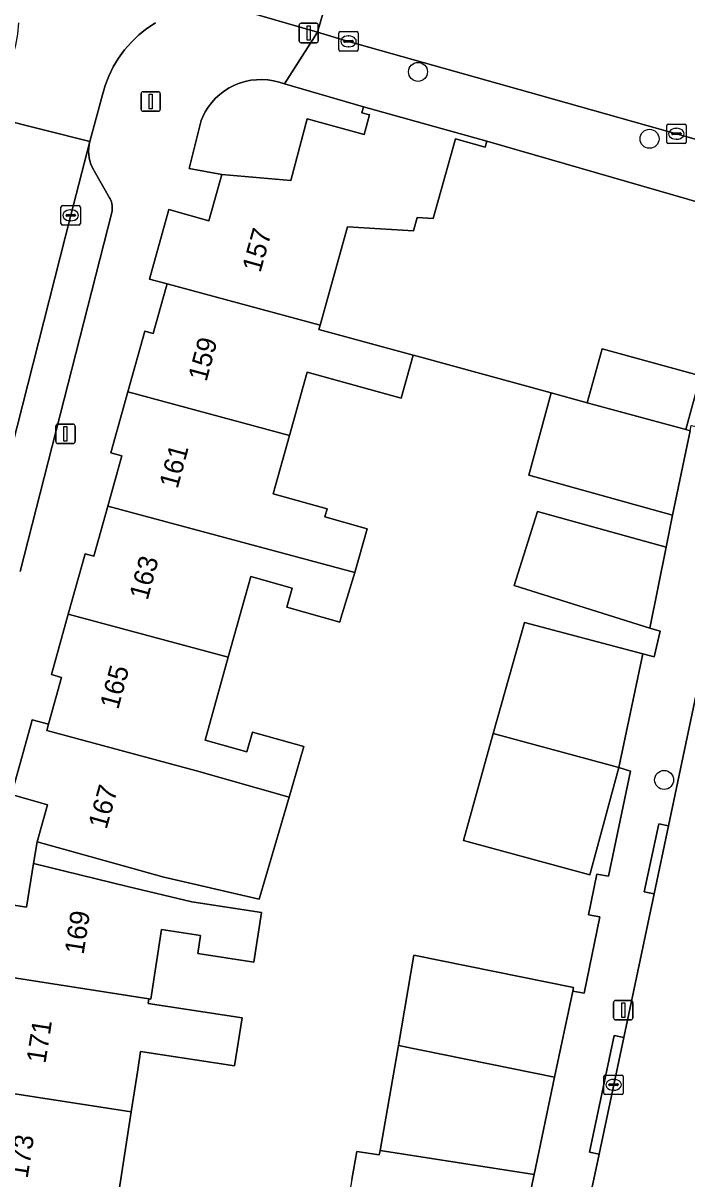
# Model space of a CAD drawing. Extents: x 161248 to 161848, y 384871 to 385383.
# Drawn here: x 161671 to 161705.2, y 385039.6 to 385099.1 of the extents above; entities that cross this region are included whole.
import ezdxf

# ---------------------------------------------------------------- set-up
doc = ezdxf.new("R2010")
doc.units = 0
for name, color, linetype in [('IMGEO_Boom', 7, 'Continuous'), ('IMGEO_Erf', 7, 'Continuous'), ('IMGEO_Hek', 7, 'Continuous'), ('IMGEO_Kolk', 7, 'Continuous'), ('IMGEO_Lichtmast', 7, 'Continuous'), ('IMGEO_Pand', 7, 'Continuous'), ('IMGEO_Pand_nummerreeks', 7, 'Continuous'), ('IMGEO_Parkeervlak_open', 7, 'Continuous'), ('IMGEO_Rijbaan_lokaal_open', 7, 'Continuous'), ('IMGEO_Voetpad_open', 7, 'Continuous')]:
    doc.layers.add(name, color=color, linetype=linetype)

msp = doc.modelspace()

# ---------------------------------------------------------------- linework, layer by layer
at = {"layer": 'IMGEO_Boom'}
for centre in [(161691.332, 385096.626), (161703.264, 385093.176), (161704.015, 385060.129)]:
    msp.add_circle(centre, 0.489, dxfattribs=at)
at = {"layer": 'IMGEO_Erf'}
for points in [[(161688.519, 385094.827), (161684.448, 385096.001), (161684.17, 385096.097), (161683.884, 385096.168), (161683.592, 385096.213), (161683.298, 385096.232), (161683.003, 385096.224), (161682.71, 385096.19), (161682.422, 385096.13), (161682.14, 385096.045), (161681.866, 385095.935), (161681.604, 385095.801), (161681.354, 385095.643), (161681.12, 385095.465), (161680.902, 385095.266), (161680.704, 385095.048), (161680.525, 385094.813), (161680.368, 385094.564), (161680.234, 385094.301), (161680.159, 385094.122), (161679.542, 385091.647), (161681.223, 385091.339), (161684.77, 385091.03), (161685.625, 385094.2), (161688.558, 385093.404), (161688.837, 385094.406), (161688.433, 385094.519)], [(161707.725, 385089.351), (161694.886, 385093.053), (161694.8, 385092.745), (161693.259, 385093.174), (161692.116, 385089.073), (161691.294, 385089.125), (161691.1, 385088.429), (161687.699, 385088.644), (161686.286, 385083.569), (161686.225, 385083.351), (161691.078, 385082.026), (161691.283, 385081.97), (161698.188, 385080.085), (161700.058, 385079.574), (161700.815, 385082.347), (161705.891, 385080.961), (161705.134, 385078.188), (161705.35, 385078.129), (161705.415, 385078.403), (161706.001, 385078.274), (161706.582, 385080.923), (161705.996, 385081.052)]]:
    msp.add_lwpolyline(points, close=True, dxfattribs=at)
msp.add_lwpolyline([(161687.923, 385039.536), (161688.171, 385040.983), (161689.338, 385040.81), (161689.376, 385041.027), (161690.323, 385046.434), (161691.123, 385051.093), (161699.354, 385049.432), (161699.313, 385049.242), (161699.897, 385049.131), (161700.704, 385053.073), (161700.114, 385053.185), (161700.543, 385055.277), (161701.146, 385055.163), (161702.28, 385060.59), (161701.685, 385060.766), (161700.183, 385055.247), (161693.674, 385057.017), (161695.208, 385062.528), (161696.828, 385068.247), (161702.916, 385066.622), (161703.511, 385066.476), (161703.805, 385067.793), (161703.28, 385067.948), (161696.289, 385070.15), (161697.492, 385073.969), (161704.117, 385072.125), (161704.441, 385073.771), (161697.038, 385075.832), (161698.188, 385080.085), (161691.283, 385081.97), (161691.078, 385082.026), (161690.459, 385079.804), (161685.613, 385081.154), (161684.703, 385077.885), (161683.867, 385074.884), (161686.648, 385074.109), (161686.53, 385073.686), (161688.704, 385073.081), (161688.074, 385070.82), (161687.355, 385068.461), (161687.301, 385068.267), (161684.57, 385069.027), (161684.846, 385070.018), (161682.712, 385070.612), (161681.553, 385066.451), (161680.364, 385062.179), (161682.518, 385061.579), (161682.801, 385062.595), (161685.451, 385061.857), (161684.685, 385059.25), (161683.137, 385053.977), (161678.383, 385055.084), (161678.24, 385055.117), (161676.52, 385055.596), (161671.703, 385056.938), (161671.506, 385055.82), (161676.367, 385054.646), (161679.669, 385053.849), (161683.273, 385053.291), (161682.878, 385050.741), (161679.981, 385051.189), (161680.123, 385052.108), (161678.111, 385052.42), (161677.556, 385048.836), (161677.453, 385048.852), (161677.416, 385048.614), (161682.266, 385047.863), (161681.882, 385045.387), (161677.033, 385046.137), (161676.885, 385045.183), (161676.55, 385043.02), (161675.859, 385038.559)], dxfattribs=at)
at = {"layer": 'IMGEO_Hek'}
for points in [[(161704.441, 385073.771), (161704.117, 385072.125)], [(161703.28, 385067.948), (161703.805, 385067.793), (161703.511, 385066.476), (161702.916, 385066.622)], [(161701.685, 385060.766), (161702.28, 385060.59), (161701.146, 385055.163), (161700.543, 385055.277), (161700.114, 385053.185), (161700.704, 385053.073), (161699.897, 385049.131), (161699.307, 385049.243), (161698.363, 385044.812)]]:
    msp.add_lwpolyline(points, dxfattribs=at)
at = {"layer": 'IMGEO_Kolk'}
for p, q in [((161687.251, 385097.773), (161687.251, 385098.625)), ((161687.326, 385098.699), (161688.178, 385098.699)), ((161687.51, 385098.193), (161687.51, 385098.205)), ((161687.553, 385098.242), (161687.951, 385098.242)), ((161687.739, 385098.479), (161687.764, 385098.479)), ((161687.994, 385098.205), (161687.994, 385098.193)), ((161688.252, 385098.625), (161688.252, 385097.773)), ((161688.178, 385097.699), (161687.326, 385097.699)), ((161687.948, 385098.156), (161687.55, 385098.156)), ((161687.762, 385097.919), (161687.737, 385097.919)), ((161704.15, 385093.01), (161704.15, 385093.862)), ((161704.225, 385093.936), (161705.077, 385093.936)), ((161704.409, 385093.43), (161704.409, 385093.442)), ((161704.452, 385093.479), (161704.85, 385093.479)), ((161704.638, 385093.716), (161704.663, 385093.716)), ((161704.893, 385093.442), (161704.893, 385093.43)), ((161705.151, 385093.862), (161705.151, 385093.01)), ((161705.077, 385092.936), (161704.225, 385092.936)), ((161704.847, 385093.393), (161704.449, 385093.393)), ((161704.661, 385093.156), (161704.636, 385093.156)), ((161672.931, 385088.806), (161672.931, 385089.658)), ((161673.006, 385089.732), (161673.858, 385089.732)), ((161673.233, 385089.275), (161673.631, 385089.275)), ((161673.419, 385089.512), (161673.444, 385089.512)), ((161673.932, 385089.658), (161673.932, 385088.806)), ((161673.858, 385088.732), (161673.006, 385088.732)), ((161673.19, 385089.226), (161673.19, 385089.238)), ((161673.628, 385089.189), (161673.23, 385089.189)), ((161673.442, 385088.952), (161673.417, 385088.952)), ((161673.674, 385089.238), (161673.674, 385089.226)), ((161700.91, 385043.992), (161700.91, 385044.844)), ((161700.985, 385044.918), (161701.837, 385044.918)), ((161701.398, 385044.698), (161701.423, 385044.698)), ((161701.911, 385044.844), (161701.911, 385043.992)), ((161701.169, 385044.412), (161701.169, 385044.424)), ((161701.607, 385044.375), (161701.209, 385044.375)), ((161701.212, 385044.461), (161701.61, 385044.461)), ((161701.421, 385044.138), (161701.396, 385044.138)), ((161701.653, 385044.424), (161701.653, 385044.412)), ((161701.837, 385043.918), (161700.985, 385043.918))]:
    msp.add_line(p, q, dxfattribs=at)
for points in [[(161687.251, 385097.773), (161687.251, 385098.625)], [(161687.326, 385098.699), (161688.178, 385098.699)], [(161688.252, 385098.625), (161688.252, 385097.773)], [(161688.178, 385097.699), (161687.326, 385097.699)], [(161704.15, 385093.01), (161704.15, 385093.862)], [(161704.225, 385093.936), (161705.077, 385093.936)], [(161705.151, 385093.862), (161705.151, 385093.01)], [(161705.077, 385092.936), (161704.225, 385092.936)], [(161672.931, 385088.806), (161672.931, 385089.658)], [(161673.006, 385089.732), (161673.858, 385089.732)], [(161673.932, 385089.658), (161673.932, 385088.806)], [(161673.858, 385088.732), (161673.006, 385088.732)], [(161700.91, 385043.992), (161700.91, 385044.844)], [(161700.985, 385044.918), (161701.837, 385044.918)], [(161701.911, 385044.844), (161701.911, 385043.992)], [(161701.837, 385043.918), (161700.985, 385043.918)]]:
    msp.add_lwpolyline(points, dxfattribs=at)
for centre, radius, start, end in [((161687.328, 385098.623), 0.0765, 91.55205, 178.44795), ((161687.328, 385098.623), 0.0765, 91.55205, 178.44795), ((161687.55, 385098.202), 0.0403, 85.87752, 175.75265), ((161687.955, 385098.204), 0.0386, 1.73085, 96.63898), ((161688.176, 385098.623), 0.0765, 1.55205, 88.44795), ((161688.176, 385098.623), 0.0765, 1.55205, 88.44795), ((161687.328, 385097.775), 0.0765, 181.55205, 268.44795), ((161687.328, 385097.775), 0.0765, 181.55205, 268.44795), ((161687.547, 385098.192), 0.0366, 178.93798, 274.71019), ((161687.951, 385098.199), 0.043, 264.86636, 352.45326), ((161688.176, 385097.775), 0.0765, 271.55205, 358.44795), ((161688.176, 385097.775), 0.0765, 271.55205, 358.44795), ((161704.227, 385093.86), 0.0765, 91.55205, 178.44795), ((161704.227, 385093.86), 0.0765, 91.55205, 178.44795), ((161704.449, 385093.439), 0.0403, 85.87752, 175.75265), ((161704.854, 385093.441), 0.0386, 1.73085, 96.63898), ((161705.075, 385093.86), 0.0765, 1.55205, 88.44795), ((161705.075, 385093.86), 0.0765, 1.55205, 88.44795), ((161704.227, 385093.012), 0.0765, 181.55205, 268.44795), ((161704.227, 385093.012), 0.0765, 181.55205, 268.44795), ((161704.446, 385093.429), 0.0366, 178.93798, 274.71019), ((161704.85, 385093.436), 0.043, 264.86636, 352.45326), ((161705.075, 385093.012), 0.0765, 271.55205, 358.44795), ((161705.075, 385093.012), 0.0765, 271.55205, 358.44795), ((161673.008, 385089.656), 0.0765, 91.55205, 178.44795), ((161673.008, 385089.656), 0.0765, 91.55205, 178.44795), ((161673.23, 385089.235), 0.0403, 85.87752, 175.75265), ((161673.635, 385089.237), 0.0386, 1.73085, 96.63898), ((161673.856, 385089.656), 0.0765, 1.55205, 88.44795), ((161673.856, 385089.656), 0.0765, 1.55205, 88.44795), ((161673.008, 385088.808), 0.0765, 181.55205, 268.44795), ((161673.008, 385088.808), 0.0765, 181.55205, 268.44795), ((161673.227, 385089.225), 0.0366, 178.93798, 274.71019), ((161673.631, 385089.232), 0.043, 264.86636, 352.45326), ((161673.856, 385088.808), 0.0765, 271.55205, 358.44795), ((161673.856, 385088.808), 0.0765, 271.55205, 358.44795), ((161700.987, 385044.842), 0.0765, 91.55205, 178.44795), ((161700.987, 385044.842), 0.0765, 91.55205, 178.44795), ((161701.835, 385044.842), 0.0765, 1.55205, 88.44795), ((161701.835, 385044.842), 0.0765, 1.55205, 88.44795), ((161700.987, 385043.994), 0.0765, 181.55205, 268.44795), ((161700.987, 385043.994), 0.0765, 181.55205, 268.44795), ((161701.209, 385044.421), 0.0403, 85.87752, 175.75265), ((161701.206, 385044.411), 0.0366, 178.93798, 274.71019), ((161701.61, 385044.418), 0.043, 264.86636, 352.45326), ((161701.614, 385044.423), 0.0386, 1.73085, 96.63898), ((161701.835, 385043.994), 0.0765, 271.55205, 358.44795), ((161701.835, 385043.994), 0.0765, 271.55205, 358.44795)]:
    msp.add_arc(centre, radius, start, end, dxfattribs=at)
for centre, major_axis, ratio, start_param, end_param in [((161687.738, 385098.199), (-0.387, 0.002), 0.722429, 4.712389, 7.853982), ((161687.763, 385098.199), (-0.39, 0.002), 0.717154, 1.570796, 4.712389), ((161704.637, 385093.436), (-0.387, 0.002), 0.722429, 4.712389, 7.853982), ((161704.662, 385093.436), (-0.39, 0.002), 0.717154, 1.570796, 4.712389), ((161673.418, 385089.232), (-0.387, 0.002), 0.722429, 4.712389, 7.853982), ((161673.443, 385089.232), (-0.39, 0.002), 0.717154, 1.570796, 4.712389), ((161701.397, 385044.418), (-0.387, 0.002), 0.722429, 4.712389, 7.853982), ((161701.422, 385044.418), (-0.39, 0.002), 0.717154, 1.570796, 4.712389)]:
    msp.add_ellipse(centre, major_axis=major_axis, ratio=ratio, start_param=start_param, end_param=end_param, dxfattribs=at)
at = {"layer": 'IMGEO_Lichtmast'}
for p, q in [((161685.204, 385098.228), (161685.204, 385099.028)), ((161685.204, 385099.028), (161685.204, 385098.228)), ((161685.304, 385099.128), (161686.094, 385099.128)), ((161686.094, 385099.128), (161685.304, 385099.128)), ((161686.194, 385099.028), (161686.194, 385098.228)), ((161686.194, 385098.228), (161686.194, 385099.028)), ((161686.094, 385098.128), (161685.304, 385098.128)), ((161685.304, 385098.128), (161686.094, 385098.128)), ((161677.059, 385094.699), (161677.059, 385095.499)), ((161677.059, 385095.499), (161677.059, 385094.699)), ((161677.159, 385095.599), (161677.949, 385095.599)), ((161677.949, 385095.599), (161677.159, 385095.599)), ((161678.049, 385095.499), (161678.049, 385094.699)), ((161678.049, 385094.699), (161678.049, 385095.499)), ((161677.949, 385094.599), (161677.159, 385094.599)), ((161677.159, 385094.599), (161677.949, 385094.599)), ((161672.664, 385077.568), (161672.664, 385078.368)), ((161672.664, 385078.368), (161672.664, 385077.568)), ((161672.764, 385078.468), (161673.554, 385078.468)), ((161673.554, 385078.468), (161672.764, 385078.468)), ((161673.654, 385078.368), (161673.654, 385077.568)), ((161673.654, 385077.568), (161673.654, 385078.368)), ((161673.554, 385077.468), (161672.764, 385077.468)), ((161672.764, 385077.468), (161673.554, 385077.468)), ((161701.514, 385048.765), (161702.304, 385048.765)), ((161702.304, 385048.765), (161701.514, 385048.765)), ((161701.414, 385047.865), (161701.414, 385048.665)), ((161701.414, 385048.665), (161701.414, 385047.865)), ((161702.404, 385048.665), (161702.404, 385047.865)), ((161702.404, 385047.865), (161702.404, 385048.665)), ((161702.304, 385047.765), (161701.514, 385047.765)), ((161701.514, 385047.765), (161702.304, 385047.765))]:
    msp.add_line(p, q, dxfattribs=at)
for points in [[(161685.624, 385099.003), (161685.774, 385099.003), (161685.774, 385098.253), (161685.624, 385098.253), (161685.624, 385099.003)], [(161677.479, 385095.474), (161677.629, 385095.474), (161677.629, 385094.724), (161677.479, 385094.724), (161677.479, 385095.474)], [(161673.084, 385078.343), (161673.234, 385078.343), (161673.234, 385077.593), (161673.084, 385077.593), (161673.084, 385078.343)], [(161701.834, 385048.64), (161701.984, 385048.64), (161701.984, 385047.89), (161701.834, 385047.89), (161701.834, 385048.64)]]:
    msp.add_lwpolyline(points, dxfattribs=at)
for centre, start, end in [((161685.304, 385099.028), 90, 180), ((161685.304, 385099.028), 90, 180), ((161686.094, 385099.028), 0, 90), ((161686.094, 385099.028), 360, 90), ((161685.304, 385098.228), 180, 270), ((161685.304, 385098.228), 180, 270), ((161686.094, 385098.228), 270, 0), ((161686.094, 385098.228), 270, 0), ((161677.159, 385095.499), 90, 180), ((161677.159, 385095.499), 90, 180), ((161677.949, 385095.499), 0, 90), ((161677.949, 385095.499), 360, 90), ((161677.159, 385094.699), 180, 270), ((161677.159, 385094.699), 180, 270), ((161677.949, 385094.699), 270, 0), ((161677.949, 385094.699), 270, 0), ((161672.764, 385078.368), 90, 180), ((161672.764, 385078.368), 90, 180), ((161673.554, 385078.368), 0, 90), ((161673.554, 385078.368), 360, 90), ((161672.764, 385077.568), 180, 270), ((161672.764, 385077.568), 180, 270), ((161673.554, 385077.568), 270, 0), ((161673.554, 385077.568), 270, 0), ((161701.514, 385048.665), 90, 180), ((161701.514, 385048.665), 90, 180), ((161702.304, 385048.665), 0, 90), ((161702.304, 385048.665), 360, 90), ((161701.514, 385047.865), 180, 270), ((161701.514, 385047.865), 180, 270), ((161702.304, 385047.865), 270, 0), ((161702.304, 385047.865), 270, 0)]:
    msp.add_arc(centre, 0.1, start, end, dxfattribs=at)
at = {"layer": 'IMGEO_Pand'}
for points in [[(161693.259, 385093.174), (161694.8, 385092.745), (161694.886, 385093.053), (161688.519, 385094.827), (161688.433, 385094.519), (161688.837, 385094.406), (161688.558, 385093.404), (161685.625, 385094.2), (161684.77, 385091.03), (161681.223, 385091.339), (161680.558, 385088.951), (161678.492, 385089.527), (161677.492, 385085.936), (161678.395, 385085.693), (161686.286, 385083.569), (161687.699, 385088.644), (161691.1, 385088.429), (161691.294, 385089.125), (161692.116, 385089.073)], [(161686.225, 385083.351), (161686.286, 385083.569), (161678.395, 385085.693), (161678.35, 385085.532), (161677.683, 385083.137), (161677.244, 385083.26), (161676.371, 385080.127), (161684.703, 385077.885), (161685.613, 385081.154), (161690.459, 385079.804), (161691.078, 385082.026)], [(161700.058, 385079.574), (161705.134, 385078.188), (161705.891, 385080.961), (161700.815, 385082.347)], [(161684.703, 385077.885), (161676.371, 385080.127), (161675.499, 385076.995), (161676.061, 385076.838), (161675.339, 385074.248), (161688.074, 385070.82), (161688.704, 385073.081), (161686.53, 385073.686), (161686.648, 385074.109), (161683.867, 385074.884)], [(161705.35, 385078.129), (161705.134, 385078.188), (161700.058, 385079.574), (161698.188, 385080.085), (161697.038, 385075.832), (161704.441, 385073.771)], [(161682.712, 385070.612), (161684.846, 385070.018), (161684.57, 385069.027), (161687.301, 385068.267), (161687.355, 385068.461), (161688.074, 385070.82), (161675.339, 385074.248), (161674.617, 385071.656), (161674.175, 385071.779), (161673.309, 385068.67), (161681.553, 385066.451)], [(161704.117, 385072.125), (161697.492, 385073.969), (161696.289, 385070.15), (161703.28, 385067.948)], [(161680.364, 385062.179), (161681.553, 385066.451), (161673.309, 385068.67), (161672.443, 385065.562), (161672.96, 385065.418), (161672.287, 385063), (161672.196, 385062.673), (161679.918, 385060.594), (161684.685, 385059.25), (161685.451, 385061.857), (161682.801, 385062.595), (161682.518, 385061.579)], [(161701.685, 385060.766), (161702.916, 385066.622), (161696.828, 385068.247), (161695.208, 385062.528)], [(161684.685, 385059.25), (161679.918, 385060.594), (161672.196, 385062.673), (161672.287, 385063), (161671.449, 385063.233), (161671.356, 385062.899), (161670.374, 385059.374), (161672.237, 385058.855), (161671.703, 385056.938), (161676.52, 385055.596), (161678.24, 385055.117), (161678.383, 385055.084), (161683.137, 385053.977)], [(161695.208, 385062.528), (161693.674, 385057.017), (161700.183, 385055.247), (161701.685, 385060.766)], [(161683.273, 385053.291), (161679.669, 385053.849), (161676.367, 385054.646), (161671.506, 385055.82), (161671.158, 385053.572), (161669.172, 385053.88), (161668.608, 385050.234), (161669.524, 385050.091), (161677.453, 385048.852), (161677.556, 385048.836), (161678.111, 385052.42), (161680.123, 385052.108), (161679.981, 385051.189), (161682.878, 385050.741)], [(161691.123, 385051.093), (161690.323, 385046.434), (161698.363, 385044.812), (161699.313, 385049.242), (161699.354, 385049.432)], [(161677.453, 385048.852), (161669.524, 385050.091), (161669.121, 385047.485), (161668.695, 385047.55), (161668.195, 385044.318), (161676.55, 385043.02), (161676.885, 385045.183), (161677.033, 385046.137), (161681.882, 385045.387), (161682.266, 385047.863), (161677.416, 385048.614)], [(161698.363, 385044.812), (161690.323, 385046.434), (161689.376, 385041.027), (161697.313, 385039.794)], [(161667.694, 385041.083), (161668.145, 385041.013), (161667.738, 385038.385), (161680.674, 385036.376), (161681.004, 385038.506), (161678.106, 385038.955), (161677.993, 385038.228), (161675.859, 385038.559), (161676.55, 385043.02), (161668.195, 385044.318)], [(161697.279, 385039.633), (161697.313, 385039.794), (161689.376, 385041.027), (161689.338, 385040.81), (161688.171, 385040.983), (161687.923, 385039.536), (161687.207, 385035.361), (161694.661, 385034.213), (161696.093, 385033.968)]]:
    msp.add_lwpolyline(points, close=True, dxfattribs=at)
at = {"layer": 'IMGEO_Parkeervlak_open'}
msp.add_lwpolyline([(161670.83, 385070.871), (161675.551, 385089.379), (161675.567, 385089.468), (161675.576, 385089.559), (161675.576, 385089.65), (161675.569, 385089.741), (161675.553, 385089.831), (161675.529, 385089.919), (161675.497, 385090.005), (161675.458, 385090.087), (161675.429, 385090.139), (161674.649, 385091.517), (161674.618, 385091.567), (161674.538, 385091.717), (161674.471, 385091.873), (161674.419, 385092.035), (161674.381, 385092.201), (161674.358, 385092.37), (161674.35, 385092.54), (161674.358, 385092.71), (161674.381, 385092.878), (161674.419, 385093.044), (161673.432, 385089.232), (161668.997, 385071.783)], dxfattribs=at)
at = {"layer": 'IMGEO_Rijbaan_lokaal_open'}
for points in [[(161682.408, 385099.761), (161686.148, 385098.677), (161688.097, 385105.371)], [(161688.097, 385105.371), (161686.148, 385098.677), (161687.752, 385098.199), (161697.639, 385095.416), (161705.809, 385093.105)], [(161670.745, 385099.15), (161670.689, 385098.575), (161670.582, 385098.007), (161670.083, 385096.175), (161669.559, 385094.249), (161674.419, 385093.044), (161675.068, 385095.448), (161675.202, 385095.915), (161675.392, 385096.41), (161675.624, 385096.886), (161675.898, 385097.34), (161676.212, 385097.767), (161676.562, 385098.164), (161676.947, 385098.529), (161677.363, 385098.858), (161677.806, 385099.148)], [(161668.997, 385071.783), (161673.432, 385089.232), (161674.419, 385093.044), (161669.559, 385094.249), (161668.602, 385090.35), (161664.237, 385073.456)], [(161706.154, 385066.816), (161704.242, 385057.766), (161703.5, 385054.255), (161701.936, 385046.853), (161700.665, 385040.837), (161699.865, 385037.053), (161699.085, 385033.36), (161698.924, 385032.597), (161698.217, 385029.252), (161697.454, 385025.658), (161696.551, 385021.375), (161694.989, 385013.98), (161694.062, 385009.595), (161693.319, 385006.112), (161692.093, 385000)]]:
    msp.add_lwpolyline(points, dxfattribs=at)
at = {"layer": 'IMGEO_Voetpad_open'}
for points in [[(161669.172, 385053.88), (161671.158, 385053.572), (161671.506, 385055.82), (161671.703, 385056.938), (161672.237, 385058.855), (161670.374, 385059.374), (161671.356, 385062.899), (161671.449, 385063.233), (161672.287, 385063), (161672.96, 385065.418), (161672.443, 385065.562), (161673.309, 385068.67), (161674.175, 385071.779), (161674.617, 385071.656), (161675.339, 385074.248), (161676.061, 385076.838), (161675.499, 385076.995), (161676.371, 385080.127), (161677.244, 385083.26), (161677.683, 385083.137), (161678.35, 385085.532), (161678.395, 385085.693), (161677.492, 385085.936), (161678.492, 385089.527), (161680.558, 385088.951), (161681.223, 385091.339), (161679.542, 385091.647), (161680.159, 385094.122), (161680.234, 385094.301), (161680.368, 385094.564), (161680.525, 385094.813), (161680.704, 385095.048), (161680.902, 385095.266), (161681.12, 385095.465), (161681.354, 385095.643), (161681.604, 385095.801), (161681.866, 385095.935), (161682.14, 385096.045), (161682.422, 385096.13), (161682.71, 385096.19), (161683.003, 385096.224), (161683.298, 385096.232), (161683.592, 385096.213), (161683.884, 385096.168), (161684.17, 385096.097), (161684.448, 385096.001), (161686.148, 385098.677), (161682.408, 385099.761)], [(161677.806, 385099.148), (161677.363, 385098.858), (161676.947, 385098.529), (161676.562, 385098.164), (161676.212, 385097.767), (161675.898, 385097.34), (161675.624, 385096.886), (161675.392, 385096.41), (161675.202, 385095.915), (161675.068, 385095.448), (161674.419, 385093.044), (161674.381, 385092.878), (161674.358, 385092.71), (161674.35, 385092.54), (161674.358, 385092.37), (161674.381, 385092.201), (161674.419, 385092.035), (161674.471, 385091.873), (161674.538, 385091.717), (161674.618, 385091.567), (161674.649, 385091.517), (161675.429, 385090.139), (161675.458, 385090.087), (161675.497, 385090.005), (161675.529, 385089.919), (161675.553, 385089.831), (161675.569, 385089.741), (161675.576, 385089.65), (161675.576, 385089.559), (161675.567, 385089.468), (161675.551, 385089.379), (161670.83, 385070.871)], [(161705.809, 385093.105), (161697.639, 385095.416), (161687.752, 385098.199), (161686.148, 385098.677), (161684.448, 385096.001), (161688.519, 385094.827), (161694.886, 385093.053), (161707.725, 385089.351)], [(161705.35, 385078.129), (161704.441, 385073.771), (161704.117, 385072.125), (161703.28, 385067.948), (161703.805, 385067.793), (161703.511, 385066.476), (161702.916, 385066.622), (161701.685, 385060.766), (161702.28, 385060.59), (161701.146, 385055.163), (161700.543, 385055.277), (161700.114, 385053.185), (161700.704, 385053.073), (161699.897, 385049.131), (161699.313, 385049.242), (161698.363, 385044.812), (161697.313, 385039.794), (161697.279, 385039.633), (161696.093, 385033.968)], [(161699.865, 385037.053), (161700.665, 385040.837), (161700.166, 385040.942), (161701.435, 385046.958), (161701.936, 385046.853), (161703.5, 385054.255), (161702.996, 385054.361), (161703.736, 385057.872), (161704.242, 385057.766), (161706.154, 385066.816)]]:
    msp.add_lwpolyline(points, dxfattribs=at)
for points in [[(161703.5, 385054.255), (161704.242, 385057.766), (161703.736, 385057.872), (161702.996, 385054.361)], [(161700.665, 385040.837), (161701.936, 385046.853), (161701.435, 385046.958), (161700.166, 385040.942)]]:
    msp.add_lwpolyline(points, close=True, dxfattribs=at)

# ---------------------------------------------------------------- texts
at = {"layer": 'IMGEO_Pand_nummerreeks'}
for s, rotation, p in [('157', 74.43868, (161683.207, 385086.239)), ('159', 74.93715, (161680.426, 385080.62)), ('161', 74.93715, (161678.939, 385075.097)), ('163', 74.93715, (161677.394, 385069.354)), ('165', 74.93715, (161675.878, 385063.721)), ('167', 74.43295, (161675.277, 385057.547)), ('169', 81.19958, (161674.094, 385051.098)), ('171', 81.17666, (161672.129, 385045.483)), ('173', 81.17622, (161671.209, 385039.56))]:
    msp.add_text(s, height=1, rotation=rotation, dxfattribs=at).set_placement(p)

doc.saveas('drawing.dxf')
